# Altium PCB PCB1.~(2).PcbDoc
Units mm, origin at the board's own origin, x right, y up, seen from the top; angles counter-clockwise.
Board outline 152.4 x 101.6 mm, 2 copper layers (Top Layer, Bottom Layer); 16 components, 39 nets, 111 pads, 0 vias.
Unrouted connection lines stored in the file: 73.
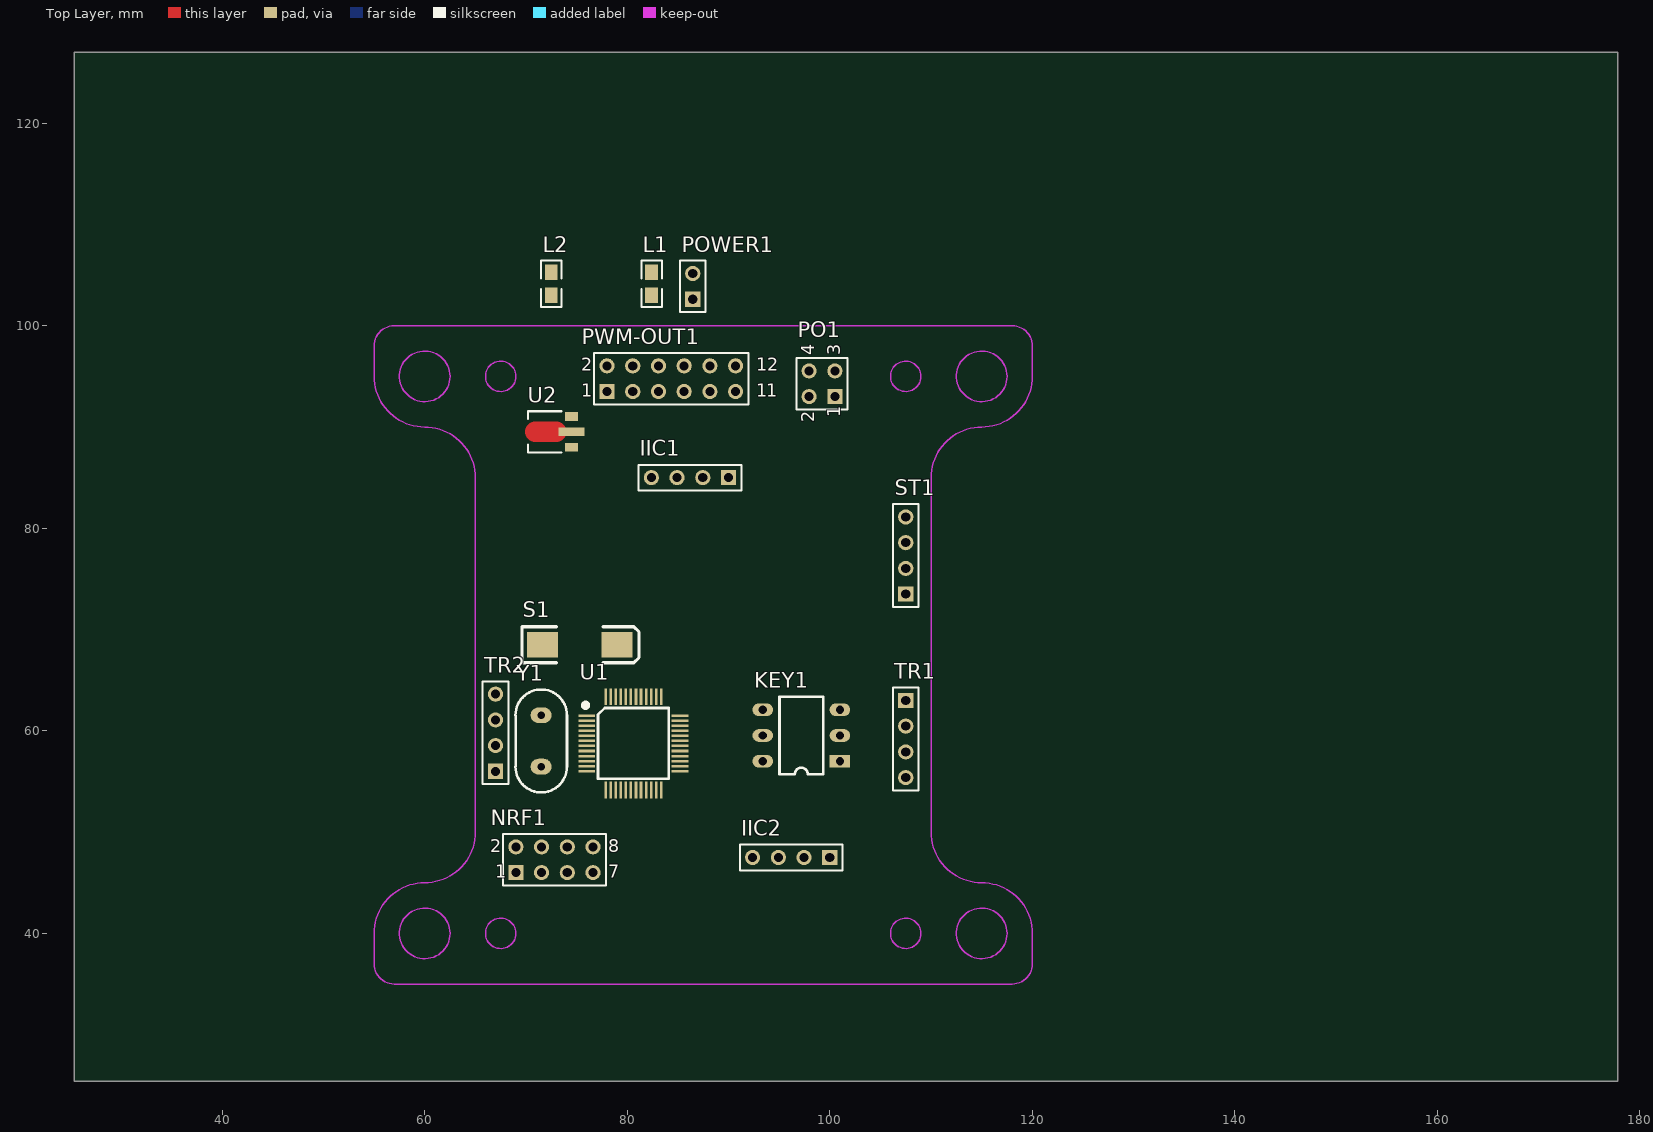
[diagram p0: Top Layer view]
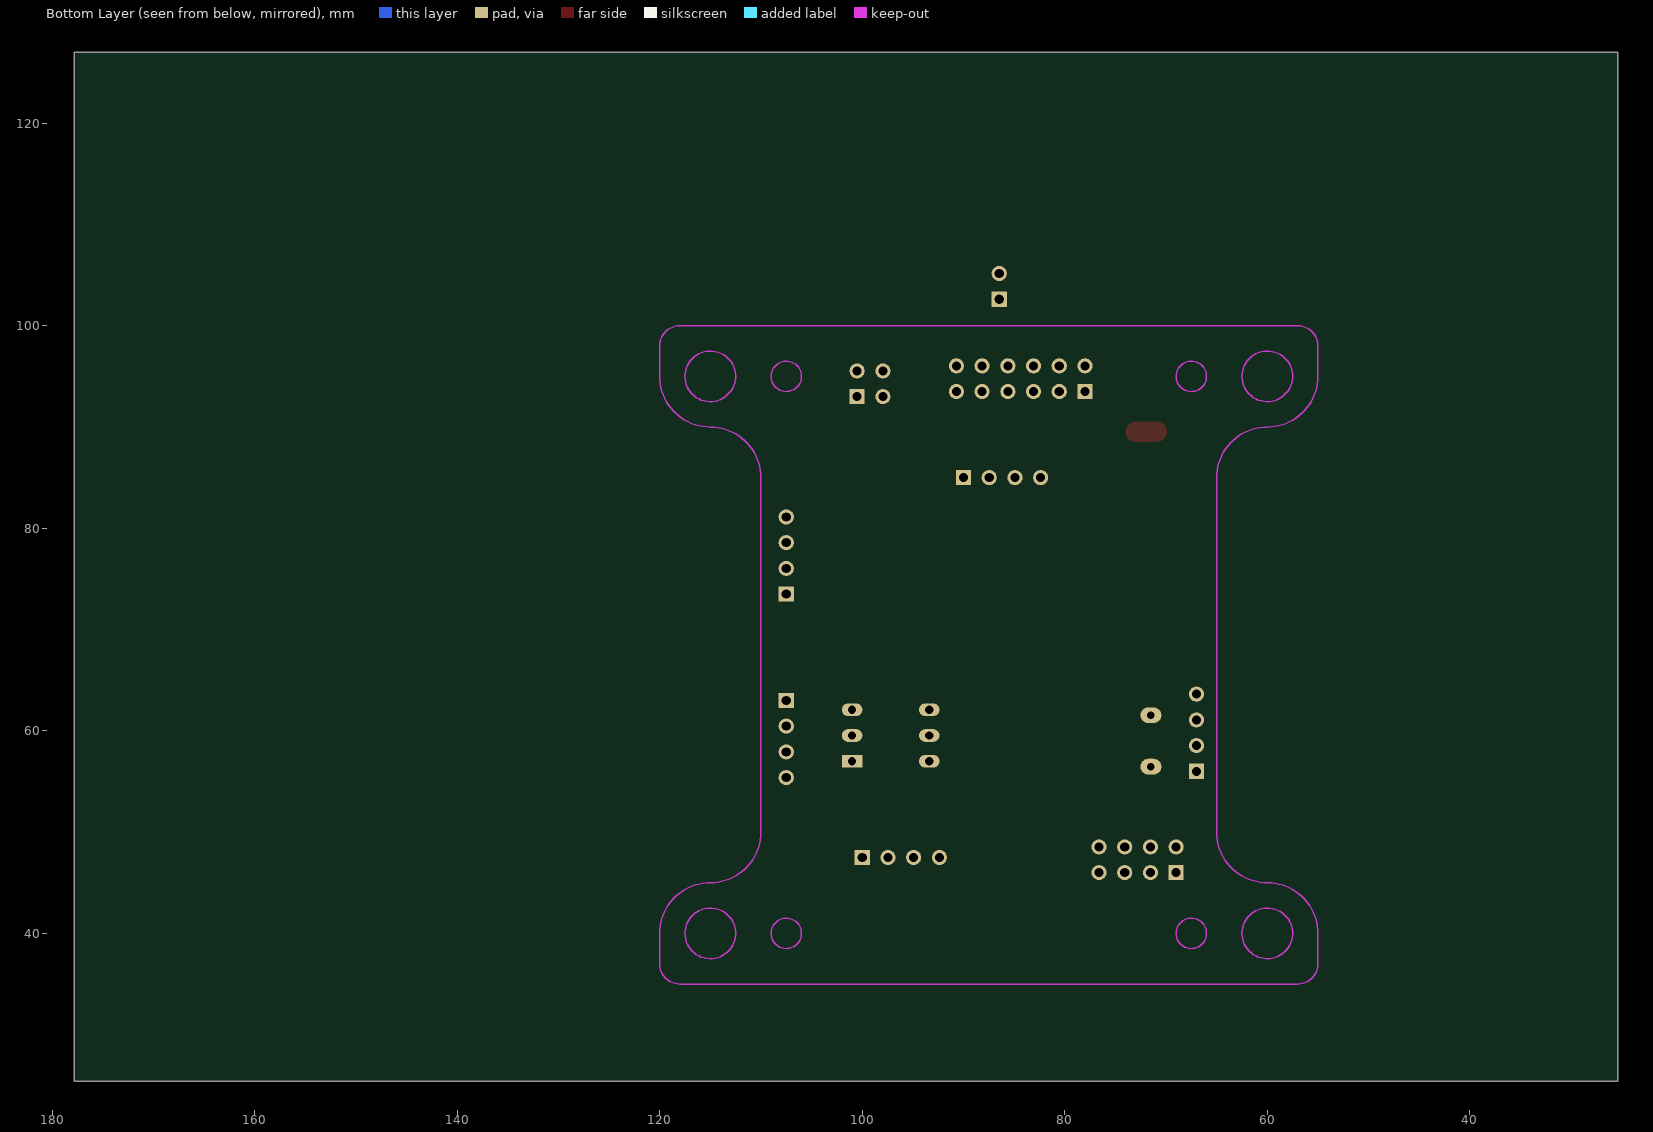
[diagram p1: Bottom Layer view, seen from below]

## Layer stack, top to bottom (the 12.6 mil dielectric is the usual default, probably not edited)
Top Solder: solder mask 0.0102, Solder Resist, Dk 3.5
Top Layer: signal copper 0.0356
Dielectric 1: dielectric 0.32, FR-4, Dk 4.8
Bottom Layer: signal copper 0.0356
Bottom Solder: solder mask 0.0102, Solder Resist, Dk 3.5

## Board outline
25.4,25.4 177.8,25.4 177.8,127 25.4,127

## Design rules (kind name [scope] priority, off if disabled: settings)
Clearance [All] p1: gap=0.178
PolygonConnect [All] p1: connectstyle=Relief reliefconductorwidth=0.254 reliefentries=4 polygonreliefangle="90 Angle" airgapwidth=0.254
RoutingVias [All] p1: holewidth=0.711 width=1.27 viastyle="Through Hole" minholewidth=0.711 minwidth=1.27 maxholewidth=0.711 maxwidth=1.27
SolderMaskExpansion [All] p1: expansion=0.102
UnpouredPolygon [All] p1: allowunpoured=FALSE
Width [All] p1: maxlimit=0.254 minlimit=0.254 preferedwidth=0.254
29 further rules are at their usual default settings.

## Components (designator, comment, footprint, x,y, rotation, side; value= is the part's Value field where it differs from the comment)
IIC1 "Header 4" HDR1X4 90,85 r180 top
IIC2 "Header 4" HDR1X4 100,47.5 r180 top
KEY1 "SW DIP-3" DIP6 101,57 r180 top
L1 "Inductor10mH" 0805 82.406,103 r90 top
L2 "Inductor" 0805 72.5,103 r90 top
NRF1 "Header 4X2" HDR2X4 69,46 r0 top
PO1 "Header 2X2" HDR2X2 100.5,93 r90 top
POWER1 "Header 2" HDR1X2 86.47,102.619 r90 top
PWM-OUT1 "Header 6X2" HDR2X6 78,93.5 r0 top
S1 "" 7243 79,68.5 r0 top
ST1 "Header 4" HDR1X4 107.5,73.5 r90 top
TR1 "Header 4" HDR1X4 107.5,63 r270 top
TR2 "Header 4" HDR1X4 67,56 r90 top
U1 "STM32F103C8T6" LQFP48S 76,61.5 r0 top
U2 "XC6203E" SOT-89 74.5,88 r90 top
Y1 "5032xtal" XTAL 71.5,59 r90 top

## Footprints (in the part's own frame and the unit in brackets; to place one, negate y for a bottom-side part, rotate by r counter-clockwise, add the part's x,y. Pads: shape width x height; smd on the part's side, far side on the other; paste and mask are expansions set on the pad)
0805 [mil]
  rect 60x50 smd: 1(0,0) 2(90,0)
  silkscreen extent -45,-40 135,40
7243 [mil]
  rect 120x100 smd: 1(0,0) 2(-290,0)
  silkscreen extent -370,-70 85,70
DIP6 [mil]
  rect 80x50 hole 32: 1(0,0)
  oval 80x50 hole 32: 2(0,-100) 3(0,-200) 4(300,-200) 5(300,-100) 6(300,0)
  silkscreen extent 65,-250 235,50
HDR1X2 [mm] "Connector; Header; 2 Position"
  rect 1.5x1.5 hole 0.9: 1(0,0)
  round 1.5 hole 0.9: 2(2.54,0)
  silkscreen extent -1.27,-1.27 3.81,1.27
HDR1X4 [mm] "Connector; Header; 4 Position"
  rect 1.5x1.5 hole 0.9: 1(0,0)
  round 1.5 hole 0.9: 2(2.54,0) 3(5.08,0) 4(7.62,0)
  silkscreen extent -1.27,-1.27 8.89,1.27
HDR2X2 [mm] "Connector; Header; 2x2 Position"
  rect 1.5x1.5 hole 0.9: 1(0,0)
  round 1.5 hole 0.9: 2(0,2.54) 3(2.54,0) 4(2.54,2.54)
  silkscreen extent -1.27,-1.27 3.81,3.81
HDR2X4 [mm] "Connector; Header; 4x2 Position"
  rect 1.5x1.5 hole 0.9: 1(0,0)
  round 1.5 hole 0.9: 2(0,2.54) 3(2.54,0) 4(2.54,2.54) 5(5.08,0) 6(5.08,2.54) 7(7.62,0) 8(7.62,2.54)
  silkscreen extent -1.27,-1.27 8.89,3.81
HDR2X6 [mm] "Connector; Header; 6x2 Position"
  rect 1.5x1.5 hole 0.9: 1(0,0)
  round 1.5 hole 0.9: 2(0,2.54) 3(2.54,0) 4(2.54,2.54) 5(5.08,0) 6(5.08,2.54) 7(7.62,0) 8(7.62,2.54) 9(10.16,0) 10(10.16,2.54) 11(12.7,0) 12(12.7,2.54)
  silkscreen extent -1.27,-1.27 13.97,3.81
LQFP48S [mil] "DPIN-0.5"
  rect 65x10 smd: 1(0.42,0.29) 2(0.42,-19.39) 3(0.42,-39.08) 4(0.42,-58.76) 5(0.42,-78.45) 6(0.42,-98.13) 7(0.42,-117.82) 8(0.42,-137.5) 9(0.42,-157.19) 10(0.42,-176.87) 11(0.42,-196.56) 12(0.42,-216.24) 25(362.63,-216.24) 26(362.63,-196.56) 27(362.63,-176.87) 28(362.63,-157.19) 29(362.63,-137.5) 30(362.63,-117.82) 31(362.63,-98.13) 32(362.63,-78.45) 33(362.63,-58.76) 34(362.63,-39.08) 35(362.63,-19.39) 36(362.63,0.29)
  rect 10x65 smd: 13(73.26,-289.08) 14(92.94,-289.08) 15(112.63,-289.08) 16(132.31,-289.08) 17(152,-289.08) 18(171.68,-289.08) 19(191.37,-289.08) 20(211.05,-289.08) 21(230.74,-289.08) 22(250.42,-289.08) 23(270.11,-289.08) 24(289.79,-289.08) 37(289.79,73.13) 38(270.11,73.13) 39(250.42,73.13) 40(230.74,73.13) 41(211.05,73.13) 42(191.37,73.13) 43(171.68,73.13) 44(152,73.13) 45(132.31,73.13) 46(112.63,73.13) 47(92.94,73.13) 48(73.26,73.13)
  silkscreen extent -10,-246 319,46
SOT-89 [mil]
  rect 34x50 smd: 1(0,0) 3(120,0)
  rect 34x100 smd: 2(60,0)
  Top Layer lines w80: 60,140 60,60
  silkscreen extent -20,40 140,170
XTAL [mil]
  oval 62x82 hole 28: 1(-100,0) 2(100,0)
  silkscreen extent -200,-100 200,100

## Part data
IIC1 IIC2 ST1 TR1 TR2: "Header, 4-Pin"
KEY1: "DIP Switch"
L1: library part Inductor
NRF1: "Header, 4-Pin, Dual row"
PO1: "Header, 2-Pin, Dual row"
POWER1: "Header, 2-Pin"
PWM-OUT1: "Header, 6-Pin, Dual row"
S1: library part 微动开关
U2: library part XC6203

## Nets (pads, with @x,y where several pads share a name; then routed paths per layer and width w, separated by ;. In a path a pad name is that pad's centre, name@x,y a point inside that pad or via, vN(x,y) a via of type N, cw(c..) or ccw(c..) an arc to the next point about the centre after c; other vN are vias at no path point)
3.3V: IIC1.1 IIC2.1 NRF1.2 PO1.1 PO1.3 ST1.4 TR1.1 TR2.1 U1.9 U1.24 U1.36 U1.48 U2.3
AD: U1.19
GND: IIC1.2 IIC2.2 KEY1.4 KEY1.5 KEY1.6 L1.1 L1.2 NRF1.1 PO1.2 PO1.4 POWER1.2 PWM-OUT1.2 PWM-OUT1.4 PWM-OUT1.6 PWM-OUT1.8 PWM-OUT1.10 PWM-OUT1.12 S1.1 ST1.2 TR1.2 TR2.2 U1.8 U1.23 U1.35 U1.47 U2.1
INC: U1.25
LED1: U1.38
MISO: NRF1.7 U1.16
MOSI: NRF1.6 U1.17
NetC1_2: U1.5 Y1.2
NetC2_2: U1.6 Y1.1
NetC3_2: S1.2 U1.7
NetD1_1: 
NetD2_1: 
NetR1_1: U1.20
NetR2_2: U1.44
PB13: KEY1.1 U1.26
PB14: KEY1.2 U1.27
PB15: KEY1.3 U1.28
PWM1: PWM-OUT1.1 U1.10
PWM2: PWM-OUT1.3 U1.11
PWM3: PWM-OUT1.5 U1.29
PWM4: PWM-OUT1.7 U1.32
PWM5: PWM-OUT1.9 U1.45
PWM6: PWM-OUT1.11 U1.46
RX1: TR1.3 U1.31
RX2: TR2.3 U1.13
SCL: IIC1.3 U1.42
SCL2: IIC2.3 U1.21
SDA: IIC1.4 U1.43
SDA2: IIC2.4 U1.22
SWCLK: ST1.3 U1.37
SWDIO: ST1.1 U1.34
TX1: TR1.4 U1.30
TX2: TR2.4 U1.12
VCC: L2.2 U2.2
VCC_BAT: L2.1 POWER1.1
W_CE: NRF1.3 U1.41
W_CSN: NRF1.4 U1.14
W_IRQ: NRF1.8 U1.18
W_SCK: NRF1.5 U1.15
pads on no net: U1.1 U1.2 U1.3 U1.4 U1.33 U1.39 U1.40

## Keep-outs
Keep-Out Layer:
  circle w0.127: c67.5,40 r1.5
  circle w0.127: c107.5,40 r1.5
  circle w0.127: c107.5,95 r1.5
  circle w0.127: c67.5,95 r1.5
  circle w0.127: c60,95 r2.5
  circle w0.127: c60,40 r2.5
  circle w0.127: c115,40 r2.5
  circle w0.127: c115,95 r2.5
  lines w0.127: 55,37 ccw(c57,37) 57,35 118,35 ccw(c118,37) 120,37 120,40 ccw(c115,40) 115,45 cw(c115,50) 110,50 110,85 cw(c115,85) 115,90 ccw(c115,95) 120,95 120,98 ccw(c118,98) 118,100 57,100 ccw(c57,98) 55,98 55,95 ccw(c60,95) 60,90 cw(c60,85) 65,85 65,50 cw(c60,50) 60,45 ccw(c60,40) 55,40 55,37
